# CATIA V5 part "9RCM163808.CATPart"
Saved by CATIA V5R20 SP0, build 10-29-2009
Part number: 9RCM163808
Revision: ANY
Definition: UNKNOWN
Nomenclature: 9RCM163808
Source: Unknown
Bounding box of the stored display mesh (mm): x -30 to 7.95, y 0 to 7.6, z -7.95 to 7.95
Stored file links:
  C:\Users\Utente\Desktop\IO LAVORO\3D X SITO CF\CUMSA\3D files RCM\RCM 163808\9RCM163808.CATPart
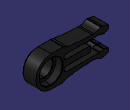
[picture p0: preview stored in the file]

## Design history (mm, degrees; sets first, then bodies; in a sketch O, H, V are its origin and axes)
Body1 "Chaflán2" (main body)
  Solid1: solid without history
